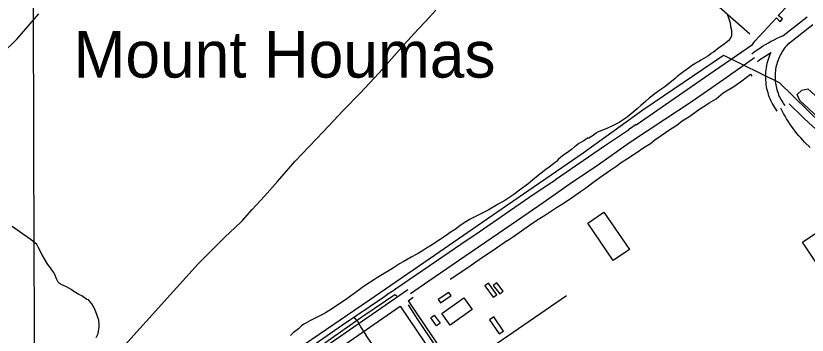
# Model space of a CAD drawing. Extents: x 3355677 to 3393573, y 612928 to 638357.
# Drawn here: x 3386069 to 3388535, y 620076 to 621070 of the extents above; entities that cross this region are included whole.
import ezdxf

# ---------------------------------------------------------------- set-up
doc = ezdxf.new("R2010")
doc.units = 0
for name, color, linetype in [('V-BLDG-OTLN', 7, 'Continuous'), ('V-GRID-MAJR', 7, 'Continuous'), ('V-ROAD-CNTR', 7, 'Continuous'), ('V-SITE-OTLN', 7, 'Continuous'), ('V-SITE-VEGE', 7, 'Continuous'), ('V-TOPO-GNAM-IDEN', 7, 'Continuous'), ('V-TOPO-SHOR', 7, 'Continuous'), ('V-UTIL-LINE', 7, 'Continuous')]:
    doc.layers.add(name, color=color, linetype=linetype)

msp = doc.modelspace()

# ---------------------------------------------------------------- linework, layer by layer
at = {"layer": 'V-BLDG-OTLN'}
for points in [[(3388605.7, 620237.3), (3388520, 620365.7), (3388641.8, 620447), (3388633.9, 620458.8), (3388657.5, 620474.4), (3388760.4, 620320.1), (3388666.1, 620257.1), (3388656.7, 620271.3)], [(3387930.7, 620307.9), (3387851.2, 620424.3), (3387901.4, 620458.6), (3387980.9, 620342.1)], [(3387530.5, 620229.3), (3387557, 620193.5), (3387568.1, 620201.7), (3387541.5, 620237.5)], [(3387557, 620230.7), (3387576.9, 620204.1), (3387588, 620212.4), (3387568.1, 620239)], [(3387392.3, 620176.2), (3387425.5, 620198.8), (3387418.7, 620208.8), (3387385.5, 620186.3)], [(3387396.3, 620143), (3387465.4, 620192.1), (3387491.5, 620155.4), (3387422.5, 620106.3)], [(3387380.4, 620104.5), (3387361.8, 620129.7), (3387372.5, 620137.6), (3387391.1, 620112.4)], [(3387545.1, 620123.1), (3387575.6, 620079.2), (3387588.6, 620088.3), (3387558.1, 620132.2)]]:
    msp.add_lwpolyline(points, close=True, dxfattribs=at)
at = {"layer": 'V-GRID-MAJR'}
msp.add_spline([(3386132.2, 618381), (3386114.6, 624440.3), (3386097, 630501.6), (3386079.3, 636562.8), (3386079.3, 636564.7)], degree=3, dxfattribs=at)
at = {"layer": 'V-ROAD-CNTR'}
for points in [[(3388362, 620952.5), (3388370.3, 620958.6), (3388378.8, 620964.5), (3388387.4, 620970.2), (3388396.2, 620975.8), (3388405.1, 620981.1), (3388414.1, 620986.3), (3388423.2, 620991.2), (3388432.4, 620996), (3388441.7, 621000.5), (3388451.1, 621004.9), (3388458.8, 621008.2), (3388534.6, 621066.9)], [(3388474.2, 620982.2), (3388552.9, 621043.2)], [(3388477.5, 620985), (3388473.6, 620980.9), (3388470.1, 620976.8), (3388466.7, 620972.6), (3388463.5, 620968.2), (3388460.4, 620963.8), (3388457.5, 620959.3), (3388454.7, 620954.6), (3388452.1, 620949.9), (3388449.6, 620945.1), (3388447.4, 620940.2), (3388445.3, 620935.2), (3388443.3, 620930.1), (3388441.6, 620925), (3388440, 620919.8), (3388438.6, 620914.6), (3388437.5, 620909.5), (3388436.5, 620904.3), (3388435.8, 620898.9), (3388435.3, 620893.5), (3388434.9, 620888.1), (3388434.8, 620882.7), (3388434.8, 620877.3), (3388435.1, 620871.9), (3388435.5, 620866.5), (3388436.2, 620861.1), (3388437, 620855.8), (3388438, 620850.4), (3388439.3, 620845.2), (3388440.7, 620839.9), (3388442.3, 620834.8), (3388444.1, 620829.7), (3388446, 620824.6), (3388448.2, 620819.6), (3388450.5, 620814.8), (3388453.1, 620810), (3388455.7, 620805.3), (3388458.6, 620800.7), (3388461.6, 620796.2), (3388465, 620791.6)], [(3387298.9, 620205.7), (3387356.4, 620244.3), (3387448.2, 620308), (3387553.1, 620379.6), (3387631.8, 620433.9), (3387712.3, 620488.8), (3387796.5, 620547.9), (3387884.9, 620607.4), (3387981.4, 620675.4), (3388091, 620748.1), (3388173.4, 620802.2), (3388275.4, 620872.9), (3388370.9, 620940.4)], [(3388379.7, 620928.3), (3388387.7, 620934.1), (3388395.7, 620939.7), (3388403.7, 620945), (3388412, 620950.2), (3388420.3, 620955.3), (3388422.3, 620956.4)], [(3388421.9, 620956.4), (3388419.9, 620952.3), (3388417.4, 620946.4), (3388415.1, 620940.3), (3388413, 620934.2), (3388411.2, 620928.1), (3388409.5, 620921.9), (3388408, 620915.4), (3388406.9, 620908.9), (3388406, 620902.5), (3388405.4, 620896), (3388405, 620889.5), (3388404.8, 620883), (3388404.8, 620876.5), (3388405.1, 620870), (3388405.7, 620863.5), (3388406.4, 620857), (3388407.4, 620850.6), (3388408.7, 620844.2), (3388410.2, 620837.9), (3388411.9, 620831.6), (3388413.8, 620825.4), (3388415.9, 620819.2), (3388418.3, 620813.2), (3388420.9, 620807.2), (3388423.7, 620801.3), (3388426.7, 620795.6), (3388430, 620789.9), (3388433.4, 620784.4), (3388437, 620779), (3388440.7, 620773.9)], [(3388543.9, 620660.5), (3388527.9, 620676.3), (3388521.4, 620683.1), (3388515.1, 620690), (3388509, 620697), (3388503, 620704.2), (3388497.2, 620711.5), (3388491.6, 620719), (3388486.1, 620726.5), (3388480.8, 620734.2), (3388475.7, 620742.1), (3388470.7, 620750), (3388466, 620758), (3388461.4, 620766.2), (3388457, 620774.4), (3388452.8, 620782.8)], [(3384754, 618381.3), (3384803.4, 618430.8), (3384863.4, 618487.9), (3384922.6, 618539.7), (3385036.5, 618629.8), (3385058.8, 618660.5), (3385089.1, 618692.4), (3385195.2, 618768.5), (3385310.7, 618848.4), (3385405.6, 618912.3), (3385700.8, 619116.3), (3385791.4, 619182.7), (3387290.6, 620218.2)], [(3387291.7, 620182.5), (3387307.6, 620193.5)], [(3387291.7, 620182.5), (3387493.6, 619884.2), (3387802.8, 619419.1), (3387898.1, 619281.9)], [(3386641.2, 619733.2), (3387267, 620165.4)], [(3387267, 620165.4), (3387468.7, 619867.5), (3387778, 619402.3), (3387873.4, 619264.9)]]:
    msp.add_lwpolyline(points, dxfattribs=at)
at = {"layer": 'V-SITE-OTLN'}
for p, q in [((3388022.4, 620777.5), (3388274.1, 620948.3)), ((3388274.1, 620948.3), (3388447.8, 620862.9)), ((3388447.8, 620862.9), (3388580.7, 620733.1)), ((3387837.4, 620644), (3388022.4, 620777.5)), ((3387567.5, 620459.2), (3387837.4, 620644)), ((3387373.9, 620324.8), (3387567.5, 620459.2)), ((3387171, 620185.4), (3387373.9, 620324.8)), ((3386969.1, 620047.9), (3387171, 620185.4))]:
    msp.add_line(p, q, dxfattribs=at)
at = {"layer": 'V-SITE-VEGE'}
for points in [[(3388284.7, 621077.5), (3388289.2, 621067), (3388294.8, 621048.6), (3388296.5, 621036.9), (3388298.7, 621025.8), (3388298.8, 621008.5), (3388296.6, 621002.9), (3388294.4, 620999), (3388290.5, 620994), (3388281.6, 620986.2), (3388276, 620982.3), (3388265.5, 620974.4), (3388258.8, 620970), (3388254.4, 620966.6), (3388247.1, 620960.4), (3388242.7, 620957.1), (3388235.5, 620952.6), (3388229.9, 620948.1), (3388225.5, 620945.3), (3388218.2, 620940.3), (3388203.8, 620931.9), (3388199.3, 620929.7), (3388191.6, 620924.6), (3388184.9, 620920.7), (3388174.9, 620914.6), (3388168.8, 620909.5), (3388157.6, 620902.2), (3388150.4, 620897.2), (3388138.2, 620887.7), (3388129.9, 620881), (3388123.2, 620874.8), (3388091, 620849.7), (3388072.6, 620836.8), (3388060.4, 620827.9), (3388042.6, 620813.9), (3388032.1, 620804.9), (3388017.1, 620791.5), (3388005.4, 620780.9), (3387986.5, 620764.7), (3387973.7, 620755.2), (3387955.4, 620741.8), (3387948.7, 620737.9), (3387926.5, 620726.6), (3387912.6, 620720.5), (3387895.3, 620713.2), (3387887, 620710.4), (3387879.2, 620707), (3387877.5, 620705.3), (3387865.3, 620695.3), (3387854.7, 620689.1), (3387852.5, 620689.7), (3387850.3, 620689.1), (3387843, 620684.1), (3387838.6, 620681.3), (3387823.6, 620672.3), (3387816.4, 620666.7), (3387810.2, 620662.2), (3387800.8, 620654.4), (3387791.9, 620647.7), (3387773, 620634.3), (3387759.7, 620623.7), (3387753.6, 620617), (3387745.8, 620610.2), (3387731.3, 620599.1), (3387720.8, 620591.8), (3387706.3, 620580.6), (3387696.9, 620572.8), (3387679.1, 620558.8), (3387664.1, 620546.5), (3387638.5, 620527.5), (3387620.8, 620514.1), (3387593, 620495), (3387571.8, 620483.3), (3387540.7, 620465.4), (3387520.1, 620454.7), (3387493.4, 620440.7), (3387484.5, 620436.8), (3387463.4, 620423.9), (3387449.5, 620414.4), (3387441.2, 620407.1), (3387435.6, 620403.2), (3387422.3, 620395.4), (3387414.5, 620389.2), (3387401.1, 620380.3), (3387391.7, 620374.1)], [(3386319.3, 620067.9), (3386325.4, 620080.7), (3386327, 620088.5), (3386329.2, 620100.2), (3386329.2, 620108.6), (3386328, 620121.9), (3386318.5, 620148.6), (3386314.5, 620158.1), (3386305.6, 620173.1), (3386301.1, 620179.8), (3386295.5, 620185.3), (3386290.5, 620187), (3386274.3, 620198.1), (3386265.4, 620202.5), (3386250.3, 620211.9), (3386242, 620217.5), (3386226.9, 620226.3), (3386218, 620230.2), (3386210.7, 620233), (3386207.9, 620235.7), (3386204, 620238), (3386201.2, 620240.2), (3386195.6, 620251.3), (3386191.1, 620264.1), (3386186.6, 620271.9), (3386177.1, 620285.2), (3386168.7, 620295.2), (3386158.1, 620313.6), (3386150.8, 620325.8), (3386139.6, 620348), (3386134, 620357.5), (3386116.7, 620372.5), (3386106.7, 620380.3), (3386089.4, 620391.3), (3386082.7, 620396.9), (3386057.5, 620414.6)], [(3387391.7, 620374.1), (3387376.7, 620364), (3387366.1, 620356.8), (3387348.9, 620346.7), (3387339.4, 620340), (3387323.3, 620329.9), (3387316.6, 620326.5), (3387300.5, 620318.1), (3387276, 620303.6), (3387264.9, 620297.4), (3387249.4, 620287.4), (3387237.7, 620280.6), (3387221.6, 620271.1), (3387212.1, 620264.4), (3387196.5, 620254.9), (3387187.1, 620249.3), (3387160.4, 620232.5), (3387147.6, 620223.5), (3387134.3, 620214), (3387111.5, 620196.7), (3387096.5, 620185.5), (3387069.8, 620168.2), (3387055.9, 620158.7), (3387033.7, 620145.2), (3387027, 620141.3), (3386997.5, 620126.2), (3386985.3, 620120), (3386970.3, 620112.2), (3386966.9, 620109.9), (3386959.7, 620104.3), (3386949.7, 620095.4), (3386933, 620083.1), (3386924.7, 620074.2)]]:
    msp.add_lwpolyline(points, dxfattribs=at)
msp.add_lwpolyline([(3388824.2, 620594.8), (3388895.4, 620546.5), (3388908.5, 620527.8), (3388920.8, 620490.8), (3388951.2, 620448.7), (3388978.2, 620438.5), (3389005.1, 620423.8), (3389026.7, 620391.1), (3389021.5, 620373.1), (3388998.3, 620364.8), (3388975.9, 620374.7), (3388945, 620403.3), (3388892.6, 620469.1), (3388609.5, 620716.8), (3388512.3, 620807), (3388503.9, 620825.6), (3388518.1, 620838.8), (3388536.5, 620842.6), (3388558.6, 620823.6), (3388589.5, 620795.1), (3388646.8, 620738.2), (3388690.7, 620691), (3388730.4, 620653)], close=True, dxfattribs=at)
at = {"layer": 'V-TOPO-SHOR'}
for p, q in [((3388356.1, 621012.9), (3388059, 621277.4)), ((3388358.4, 620888.3), (3388362.4, 620882.8)), ((3387478, 620285.3), (3387422.9, 620249.4))]:
    msp.add_line(p, q, dxfattribs=at)
for points in [[(3386718.1, 620379.1), (3386739.1, 620399), (3386750.4, 620409.3), (3386774.9, 620433.2), (3386805.5, 620466.6), (3386844.2, 620509), (3386884.4, 620554), (3386939.8, 620617.2), (3387026.6, 620709.3), (3387090.4, 620776.2), (3387142, 620829.3), (3387199.7, 620892.2), (3387279.6, 620981.6), (3387322.8, 621029.3), (3387345.7, 621053.1), (3387377.6, 621088.5)], [(3385996.2, 620920.8), (3386024.4, 620950.7), (3386073.5, 620999.3), (3386141.2, 621076.4)], [(3387922.9, 620590.3), (3387938.5, 620601.4), (3387955.3, 620613), (3387975.1, 620626), (3388001.7, 620643.4), (3388026, 620660.1), (3388046.4, 620673.1), (3388060, 620683.8), (3388083.3, 620699.5), (3388093.7, 620706.8), (3388107, 620715.8), (3388128.4, 620730.2), (3388145.9, 620742.8), (3388166.3, 620755.5), (3388184.8, 620768.9), (3388200.3, 620780.5), (3388215.9, 620790.5), (3388229.5, 620798.9), (3388250.9, 620812), (3388273.2, 620830.2), (3388306.6, 620850.6), (3388330.9, 620868.3), (3388358.4, 620888.3)], [(3388478.4, 620796.4), (3388521.8, 620755.1), (3388542.3, 620735.5), (3388560.2, 620719.3), (3388579.1, 620700), (3388608.6, 620674.9), (3388633.4, 620651), (3388665.2, 620619.7), (3388694.1, 620593), (3388720.9, 620568.5), (3388744.4, 620545.9), (3388768.6, 620524.3), (3388793.1, 620501.4), (3388815.3, 620480.2), (3388840.8, 620456), (3388860, 620437.6), (3388879.6, 620419.5), (3388909.7, 620389.9), (3388950.8, 620351.8)], [(3387600.9, 620370.5), (3387619.7, 620382.5), (3387644.9, 620401.1), (3387669.5, 620418.2), (3387692.9, 620433.5), (3387719.8, 620450.6), (3387753.8, 620472.9), (3387777.5, 620488.3), (3387804.1, 620506), (3387828.4, 620523), (3387844.2, 620534), (3387866.6, 620551), (3387896.1, 620571.7), (3387922.9, 620590.3)], [(3386718.1, 620379.1), (3386637.2, 620297.8), (3386560.1, 620212.1), (3386390.4, 620023.2), (3386268.2, 619888.1), (3386165.9, 619778.1), (3386030.2, 619634.6), (3385876, 619470.6), (3385759, 619333.4)], [(3387600.9, 620370.5), (3387556.2, 620339.2), (3387519.7, 620315.5), (3387478, 620285.3)], [(3385903, 619272.2), (3385963, 619313.4), (3386019.6, 619352), (3386095.5, 619404.7), (3386203.5, 619479.2), (3386243.7, 619507), (3386297.7, 619543.3), (3386365.4, 619591), (3386425.4, 619631.9), (3386502.1, 619686.5), (3386601.1, 619754.4), (3386655.8, 619793), (3386724, 619837.7), (3386809.6, 619898.4), (3386857.3, 619931.2), (3386900.4, 619962.5), (3386939.9, 619987.4), (3386980.5, 620016.4), (3387024.8, 620046.2), (3387070.2, 620078.2), (3387147.3, 620132.8), (3387220.7, 620182.5), (3387249.7, 620202), (3387256.1, 620198.3)], [(3387291.4, 620170.2), (3387320.4, 620124.7), (3387376.2, 620042.8), (3387436.5, 619954.2), (3387479.3, 619894.2), (3387529.7, 619821.6), (3387577.4, 619754.6), (3387635.8, 619667.5), (3387696.9, 619579.6), (3387743.5, 619513), (3387792, 619441.9), (3387847.8, 619358.5)]]:
    msp.add_lwpolyline(points, dxfattribs=at)
at = {"layer": 'V-UTIL-LINE'}
for points in [[(3388228.6, 620887.3), (3388364.9, 620980.8), (3388371.5, 620991.8), (3388439, 621063.9), (3388450.8, 621051.8), (3388458.2, 621060.7), (3388445, 621071.5), (3388539.5, 621170.6), (3388504.2, 621199.6), (3388494.7, 621191.2), (3388484.3, 621201.4), (3388494.5, 621211.1), (3388432, 621272.5), (3388421.9, 621262.1), (3388412.2, 621272.2), (3388421.7, 621281.9), (3388387.7, 621311.6), (3388459.9, 621386.4), (3388464.6, 621392), (3388367.7, 621478.2), (3388466, 621591.8), (3388563.1, 621498)], [(3386964.9, 620022.8), (3387087.5, 620107.6), (3387211.4, 620191.6), (3387226.5, 620202.4), (3387224.8, 620202), (3387249.7, 620217.9), (3387249.1, 620217.5), (3387380.2, 620307.6), (3387475.3, 620372.2), (3387474.9, 620371.8), (3387500.5, 620389.3), (3387499.2, 620388.3), (3387680.8, 620513.7), (3387726.4, 620543.7), (3387727.7, 620544.7), (3387751, 620559.8), (3387750.3, 620560.5), (3387903.4, 620665), (3387977.8, 620715.5), (3387978.5, 620716.1), (3388002.1, 620732.6), (3388001.8, 620731), (3388133.9, 620822.1), (3388228.6, 620887.3)], [(3387533, 619534.6), (3387518.5, 619556.2), (3387334.5, 619819), (3387303.1, 619871.2), (3387459.5, 619977.4), (3387585.4, 620062.2), (3387785, 620198.9)], [(3387303.1, 619871.2), (3387292.4, 619889.1), (3387161.1, 620074.5), (3387161.8, 620074.5), (3387144.3, 620101.3), (3387134.3, 620118.5), (3387132, 620121.4), (3387123.3, 620131.9)]]:
    msp.add_lwpolyline(points, dxfattribs=at)

# ---------------------------------------------------------------- texts
at = {"layer": 'V-TOPO-GNAM-IDEN'}
msp.add_text('Mount Houmas', height=145, rotation=359.9881, dxfattribs=at).set_placement((3386249, 620878.2))

doc.saveas('drawing.dxf')
